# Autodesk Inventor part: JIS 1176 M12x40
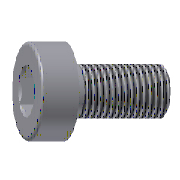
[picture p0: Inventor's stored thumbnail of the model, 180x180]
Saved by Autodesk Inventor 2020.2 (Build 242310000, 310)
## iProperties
Manager: www.cadconsulting.pl
Company: Fabian Stasiak CAD Consulting
IsCustomPart: 0
Created: 2014-02
Part Number: JIS 1176 M12x40
Material: Stal, miękka
Description: Cylinder Head Cap Screw
Document SubType Name: Modeling
Designer: F.Stasiak
Standard Revision: 1
Language: pl-PL
Size Designation: M12x40
Categories: <MemberInstance><Categories><Category DisplayName="Forma wtryskowa" InternalName="349578f2-f4d4-4954-8c09-8e99297a61c0" Mnemonic="MOLD"><Category DisplayName="C
Mass: 0.133121 g
Surface Area: 2.01441 cm^2
Volume: 0.133121 cm^3
Density: 7.85 g/cm^3
Appearance: Częściowo polerowana
Catalog Web Link: www.expertbooks.pl
Author: F.Stasiak
Subject: Zbiór ćwiczeń. Autodesk Inventor 2020. Kurs Professional
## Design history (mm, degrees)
sketch "Sketch1"
  geometry: L1 (0, -50.4)-(0, 22.4) reference; L2 (5.774, 12)-(9, 12); L3 (9, 12)-(9, 0); L4 (9, 0)-(6, 0); L5 (6, 0)-(6, -40); L6 (6, -40)-(0, -40); L7 (0, 2.996)-(0, -40); L8 (0, 2.996)-(5, 6); L9 (5, 6)-(5, 11.226); L10 (5, 11.226)-(5.774, 12); 1 further point
  constraints: 18 end point, 4 vertical, 3 horizontal, 2 point on line
  dimensions: "d0" = 18 diameter of L3 L1 (= dk); "d1" = 12 distance between parallel lines of L4 L2 (= k); "d2" = 12 diameter of L5 L1 (= d); "d3" = 40 distance between parallel lines of L6 L4 (= L); "d4" = 59 deg angle of L1 L8; "d5" = 45 deg angle of L1 L10; "d6" = 10 diameter of L9 L1 (= sw); "d7" = 11.54701 diameter of L2.start L1 (= 1.1547 x sw); "d8" = 6 distance from line of L8.end L2 (= t)
revolve "Revolution1" sketch "Sketch1" stored, may be unused: angle "d44" = 90 deg
sketch "Sketch2"
  geometry: L1 (0, 5.774)-(5, 2.887); L2 (5, 2.887)-(5, -2.887); L3 (5, -2.887)-(0, -5.774); L4 (0, -5.774)-(-5, -2.887); L5 (-5, -2.887)-(-5, 2.887); L6 (-5, 2.887)-(0, 5.774); 3 further points
  constraints: 12 end point, 2 vertical alignment, 1 coincident, 14 other
extrude "Extrusion1" cut sketch "Sketch2" taper "d9" = 0 deg; stored distance "d45" = 10
thread "Thread1" dims "d10" = 35.625 (= b), "d11" = 0
chamfer "Chamfer1" distance "d12" = 0.875 (= 0.5 x P); stored, may be unused: second distance "d50" = 2, angle "d51" = 45 deg
fillet "Fillet1" dims "d13" = 0.875 (= 0.5 x P)
body "Solid1"
other parameters: "d" = 12 [user parameter; used in 1 equation term], "L" = 40 [user parameter; used in 1 equation term], "dk" = 18 [user parameter; used in 1 equation term], "b" = 35.625 [user parameter; used in 1 equation term], "k" = 12 [user parameter; used in 1 equation term], "sw" = 10 [user parameter; used in 2 equation terms], "t" = 6 [user parameter; used in 1 equation term], "P" = 1.75 [user parameter; used in 2 equation terms], "d14" = 0, "d15" = 0, "d55" = 0
